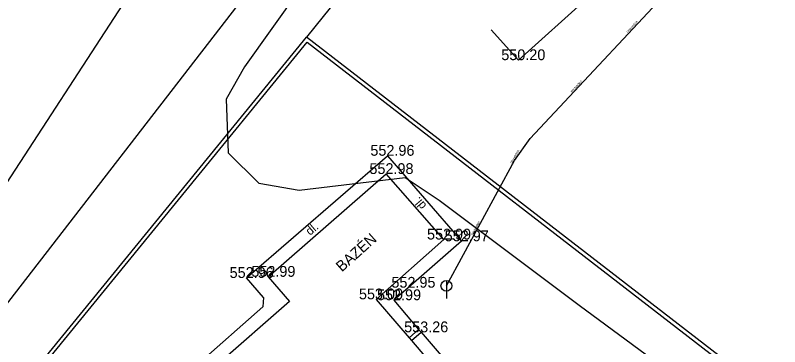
# Model space of a CAD drawing. Extents: x -669995 to -669686, y -1125551 to -1125263.
# Drawn here: x -669941 to -669887.8, y -1125424.8 to -1125401.7 of the extents above; entities that cross this region are included whole.
import ezdxf

# ---------------------------------------------------------------- set-up
doc = ezdxf.new("R2010")
doc.units = 0
for name, color, linetype in [('G_Bod_tecka', 7, 'Continuous'), ('G_Bod_vyska', 7, 'Continuous'), ('G_Breh_Teren', 7, 'Continuous'), ('G_Budovy_Objekty', 7, 'Continuous'), ('G_Cesty_Schody', 7, 'Continuous'), ('G_Plochy_zpevnene', 7, 'Continuous'), ('G_Ploty', 7, 'Continuous'), ('G_Popisy_povrchu', 7, 'Continuous'), ('G_Poznamky_odkaz', 7, 'Continuous'), ('G_Site-kanalizace', 7, 'Continuous'), ('G_Z_KANAL_podz_kotovane', 7, 'Continuous'), ('G_Z_SPOJE_podz_geodeticky', 7, 'Continuous'), ('Vrstva 13', 7, 'Continuous'), ('Vrstva 3', 7, 'Continuous')]:
    doc.layers.add(name, color=color, linetype=linetype)

msp = doc.modelspace()

# ---------------------------------------------------------------- linework, layer by layer
at = {"layer": 'G_Bod_tecka'}
for p, q in [((-669905.93, -1125404.82), (-669905.93, -1125404.82)), ((-669915.07, -1125411.47), (-669915.07, -1125411.47)), ((-669915.15, -1125412.74), (-669915.15, -1125412.74)), ((-669911.14, -1125417.3), (-669911.14, -1125417.3)), ((-669909.91, -1125417.42), (-669909.91, -1125417.42)), ((-669924.87, -1125419.97), (-669924.87, -1125419.97)), ((-669923.37, -1125419.89), (-669923.37, -1125419.89)), ((-669913.62, -1125420.65), (-669913.62, -1125420.65)), ((-669915.84, -1125421.46), (-669915.84, -1125421.46)), ((-669914.62, -1125421.52), (-669914.62, -1125421.52)), ((-669912.72, -1125423.75), (-669912.72, -1125423.75))]:
    msp.add_line(p, q, dxfattribs=at)
at = {"layer": 'G_Breh_Teren'}
for p, q in [((-669918.8, -1125378.37), (-669945.39, -1125419.19)), ((-669943.66, -1125424.48), (-669910.9, -1125382.13)), ((-669907.12, -1125386.45), (-669920.7, -1125403.21))]:
    msp.add_line(p, q, dxfattribs=at)
at = {"layer": 'G_Budovy_Objekty'}
for p, q in [((-669900.17, -1125399.61), (-669905.93, -1125404.82)), ((-669907.85, -1125402.7), (-669905.93, -1125404.82)), ((-669923.37, -1125419.89), (-669915.15, -1125412.74)), ((-669911.14, -1125417.3), (-669915.15, -1125412.74)), ((-669915.84, -1125421.46), (-669911.14, -1125417.3)), ((-669923.37, -1125419.89), (-669921.89, -1125421.62)), ((-669921.89, -1125421.62), (-669932.23, -1125430.65)), ((-669915.84, -1125421.46), (-669913.56, -1125424.13)), ((-669913.56, -1125424.13), (-669913.39, -1125424.33)), ((-669913.39, -1125424.33), (-669909.81, -1125428.52))]:
    msp.add_line(p, q, dxfattribs=at)
at = {"layer": 'G_Cesty_Schody'}
for p, q in [((-669913.56, -1125424.13), (-669912.89, -1125423.55)), ((-669913.39, -1125424.33), (-669912.72, -1125423.75))]:
    msp.add_line(p, q, dxfattribs=at)
at = {"layer": 'G_Plochy_zpevnene'}
for p, q in [((-669924.87, -1125419.97), (-669915.07, -1125411.47)), ((-669915.07, -1125411.47), (-669909.91, -1125417.42)), ((-669909.91, -1125417.42), (-669913.62, -1125420.65)), ((-669923.69, -1125421.33), (-669924.87, -1125419.97)), ((-669913.62, -1125420.65), (-669914.62, -1125421.52)), ((-669923.69, -1125421.33), (-669923.74, -1125421.98)), ((-669914.62, -1125421.52), (-669912.89, -1125423.55)), ((-669923.74, -1125421.98), (-669928.75, -1125426.39)), ((-669912.89, -1125423.55), (-669912.72, -1125423.75)), ((-669912.72, -1125423.75), (-669902.64, -1125435.41))]:
    msp.add_line(p, q, dxfattribs=at)
at = {"layer": 'G_Ploty'}
for p, q in [((-669940.74, -1125427.77), (-669920.7, -1125403.21)), ((-669940.55, -1125427.93), (-669920.66, -1125403.56)), ((-669879.12, -1125435.3), (-669920.7, -1125403.21)), ((-669920.66, -1125403.56), (-669879.52, -1125435.31))]:
    msp.add_line(p, q, dxfattribs=at)
at = {"layer": 'G_Site-kanalizace'}
msp.add_line((-669910.96, -1125420.145), (-669910.96, -1125421.395), dxfattribs=at)
msp.add_circle((-669910.96, -1125420.52), 0.375, dxfattribs=at)
at = {"layer": 'G_Z_KANAL_podz_kotovane'}
msp.add_lwpolyline([(-669910.96, -1125420.52), (-669906.21, -1125411.8), (-669905.13, -1125410.27), (-669893.86, -1125398.23), (-669885.11, -1125389.05), (-669885.76, -1125384.23), (-669877.39, -1125372.81), (-669865.05, -1125355.75)], dxfattribs=at)
at = {"layer": 'G_Z_SPOJE_podz_geodeticky'}
msp.add_lwpolyline([(-669882.04, -1125353.23), (-669888.47, -1125362.55), (-669902.63, -1125378.37), (-669910.95, -1125386.95), (-669915.3, -1125391.93), (-669919.2, -1125397.1), (-669925.01, -1125405.29), (-669926.3, -1125407.53), (-669926.15, -1125411.27), (-669924.02, -1125413.38), (-669921.22, -1125413.87), (-669913.82, -1125412.99), (-669911.46, -1125414.56), (-669901.71, -1125421.87), (-669885.88, -1125433.52)], dxfattribs=at)
at = {"layer": 'Vrstva 13'}
msp.add_lwpolyline([(-669910.962, -1125420.524), (-669906.21, -1125411.8), (-669905.13, -1125410.27), (-669893.86, -1125398.23), (-669885.11, -1125389.05), (-669885.76, -1125384.23), (-669877.39, -1125372.81), (-669865.05, -1125355.75)], dxfattribs=at)

# ---------------------------------------------------------------- texts
at = {"layer": 'G_Bod_vyska'}
for s, p in [('550.20', (-669907.137, -1125404.82)), ('552.96', (-669916.25, -1125411.47)), ('552.98', (-669916.316, -1125412.74)), ('552.99', (-669912.308, -1125417.3)), ('552.97', (-669911.076, -1125417.42)), ('552.99', (-669924.538, -1125419.89)), ('552.96', (-669926.05, -1125419.97)), ('552.95', (-669914.786, -1125420.65)), ('553.00', (-669917.047, -1125421.46)), ('552.99', (-669915.788, -1125421.52)), ('553.26', (-669913.898, -1125423.75))]:
    msp.add_text(s, height=0.75, dxfattribs=at).set_placement(p)
at = {"layer": 'G_Popisy_povrchu'}
for rotation, p in [(130.442, (-669912.313, -1125414.922)), (40.8166, (-669920.448, -1125417.051))]:
    msp.add_text('dl.', height=0.6, rotation=rotation, dxfattribs=at).set_placement(p)
at = {"layer": 'G_Poznamky_odkaz'}
msp.add_text('BAZÉN', height=0.75, rotation=41.9097, dxfattribs=at).set_placement((-669918.235, -1125419.589))
at = {"layer": 'Vrstva 3'}
for rotation, p in [(46.8836, (-669898.34, -1125402.94)), (46.8436, (-669902.217, -1125407.083)), (59.1869, (-669906.406, -1125412.026)), (61.4316, (-669909.112, -1125417.016))]:
    msp.add_text('neuveden', height=0.1755, rotation=rotation, dxfattribs=at).set_placement(p)

doc.saveas('drawing.dxf')
